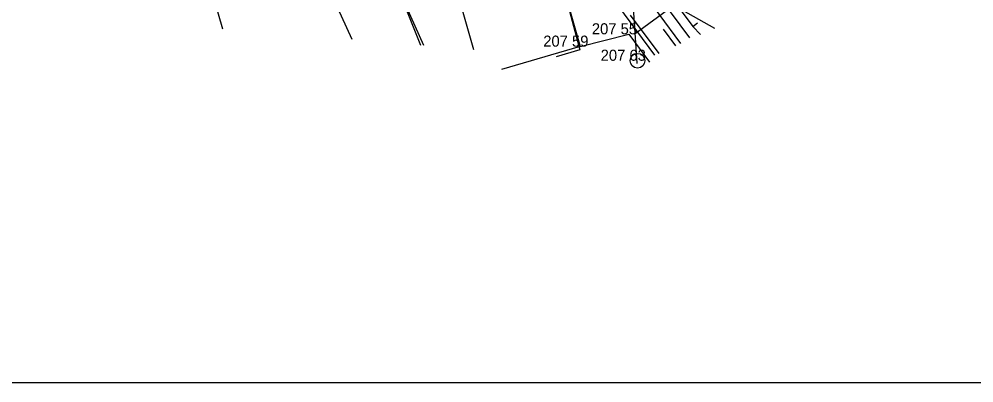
# Model space of a CAD drawing. Extents: x -524633 to -524336, y -1187893 to -1187683.
# Drawn here: x -524526.1 to -524461.3, y -1187892.7 to -1187868 of the extents above; entities that cross this region are included whole.
import ezdxf

# ---------------------------------------------------------------- set-up
doc = ezdxf.new("R2010")
doc.units = 0
for name, color, linetype in [('Hranice parcel', 7, 'Continuous'), ('Vrstva 1', 7, 'Continuous'), ('Vrstva 10', 7, 'Continuous'), ('Vrstva 27', 7, 'Continuous'), ('Vrstva 3', 7, 'Continuous'), ('Vrstva 4', 7, 'Continuous'), ('Vrstva 5', 7, 'Continuous'), ('Vrstva 53', 7, 'Continuous'), ('Vrstva 54', 7, 'Continuous'), ('Vrstva 55', 7, 'Continuous'), ('Vrstva 58', 7, 'Continuous'), ('Vrstva 63', 7, 'Continuous'), ('Vrstva 7', 7, 'Continuous')]:
    doc.layers.add(name, color=color, linetype=linetype)

msp = doc.modelspace()

# ---------------------------------------------------------------- linework, layer by layer
at = {"layer": 'Hranice parcel'}
for p, q in [((-524482.931, -1187870.415), (-524490.77, -1187859.73)), ((-524490.77, -1187859.73), (-524488.01, -1187870.05)), ((-524488.01, -1187870.05), (-524489.621, -1187870.511))]:
    msp.add_line(p, q, dxfattribs=at)
for points in [[(-524495.216, -1187870.042), (-524498.24, -1187859.41)], [(-524503.468, -1187869.35), (-524506.52, -1187862.68), (-524513.33, -1187865)], [(-524513.33, -1187865), (-524512.286, -1187868.611)], [(-524498.616, -1187869.757), (-524500.67, -1187865.14)], [(-524500.67, -1187865.14), (-524498.841, -1187869.738)]]:
    msp.add_lwpolyline(points, dxfattribs=at)
at = {"layer": 'Vrstva 1'}
for p, q in [((-524484.702, -1187868.991), (-524484.702, -1187868.991)), ((-524488.002, -1187869.83), (-524488.002, -1187869.83)), ((-524484.104, -1187870.787), (-524484.104, -1187870.787)), ((-524484.15, -1187870.97), (-524484.15, -1187870.97))]:
    msp.add_line(p, q, dxfattribs=at)
at = {"layer": 'Vrstva 10'}
msp.add_line((-524480.556, -1187869.239), (-524482.76, -1187866.24), dxfattribs=at)
at = {"layer": 'Vrstva 27'}
msp.add_circle((-524484.104, -1187870.787), 0.5, dxfattribs=at)
at = {"layer": 'Vrstva 5'}
for p, q in [((-524492.809, -1187852.928), (-524488.001, -1187869.83)), ((-524488.001, -1187869.83), (-524493.348, -1187871.371))]:
    msp.add_line(p, q, dxfattribs=at)
at = {"layer": 'Vrstva 53'}
for points in [[(-524484.59, -1187867.7), (-524482.658, -1187870.291)], [(-524482.358, -1187868.653), (-524481.524, -1187869.775)]]:
    msp.add_lwpolyline(points, dxfattribs=at)
at = {"layer": 'Vrstva 54'}
for p, q in [((-524484.999, -1187862.241), (-524480.338, -1187868.457)), ((-524480.338, -1187868.457), (-524480.018, -1187868.217)), ((-524479.822, -1187868.999), (-524480.338, -1187868.457))]:
    msp.add_line(p, q, dxfattribs=at)
at = {"layer": 'Vrstva 55'}
for p, q in [((-524484.13, -1187870.96), (-524485.38, -1187851.41)), ((-524478.3, -1187864.57), (-524484.257, -1187868.964)), ((-524484.136, -1187870.964), (-524484.13, -1187870.96))]:
    msp.add_line(p, q, dxfattribs=at)
at = {"layer": 'Vrstva 58'}
for points in [[(-524481.164, -1187869.61), (-524484.11, -1187865.62), (-524490.8, -1187855.27)], [(-524484.11, -1187865.62), (-524478.876, -1187868.569)]]:
    msp.add_lwpolyline(points, dxfattribs=at)
at = {"layer": 'Vrstva 63'}
msp.add_lwpolyline([(-524632.797, -1187892.658), (-524632.797, -1187682.658), (-524335.797, -1187682.658), (-524335.797, -1187892.658)], close=True, dxfattribs=at)
at = {"layer": 'Vrstva 7'}
for points in [[(-524488.001, -1187869.83), (-524484.702, -1187868.991)], [(-524484.702, -1187868.991), (-524483.292, -1187870.89)]]:
    msp.add_lwpolyline(points, dxfattribs=at)

# ---------------------------------------------------------------- texts
at = {"layer": 'Vrstva 3'}
msp.add_text('207 55 ', height=0.75, dxfattribs=at).set_placement((-524487.202, -1187868.991))
at = {"layer": 'Vrstva 4'}
for s, p in [('207 59 ', (-524490.502, -1187869.83)), ('207 63 ', (-524486.604, -1187870.787))]:
    msp.add_text(s, height=0.75, dxfattribs=at).set_placement(p)

doc.saveas('drawing.dxf')
